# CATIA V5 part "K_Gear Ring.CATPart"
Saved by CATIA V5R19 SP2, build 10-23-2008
Part number: Gear Ring
Bounding box of the stored display mesh (mm): x -39.5 to 39.5, y -39.5 to 39.5, z -6 to 12
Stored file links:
  G:\Khaled_CFAO_2011\ST2M\ST2M_GR1\bgaltie\bgaltie\Khaled\CAD_thinkMOTION\K_Gear Ring.CATPart
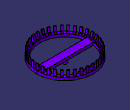
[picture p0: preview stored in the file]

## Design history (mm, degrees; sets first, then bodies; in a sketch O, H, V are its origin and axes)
AxisSystem1: origin (0, 0, 0), X (1, 0, 0), Y (0, 1, 0), Z (0, 0, 1)
Body1 (main body)
  Sketch1 on XY plane of AxisSystem1, origin (0, 0, 0), H (1, 0, 0), V (0, 1, 0)
    arc A1 centre (0, 0) radius 39.5 from (-39.5, 0) to (39.5, 0) ccw
    point P1 (0, 0)
    point P2 (39.5, 0)
    arc A2 centre (0, 0) radius 35 from (-34.641, -5) to (34.641, -5) ccw
    point P3 (0, 0)
    reference projected point E1 (0, 0) from vertex [YZ plane of AxisSystem1 | ZX plane of AxisSystem1 | XY plane of AxisSystem1]
    point P4 (34.641, -5)
    point P5 (-34.641, -5)
    line L1 (-34.641, -5) -> (34.641, -5)
    point P6 (-34.641, -5)
    point P7 (34.641, -5)
    reference projected point E2 (0, 0) from vertex [YZ plane of AxisSystem1 | ZX plane of AxisSystem1 | XY plane of AxisSystem1]
    line L2 (39.5, 0) -> (-39.5, 0)
    radius A1 = 39.5
    radius A2 = 35
    length L2 = 79
    distance L2 L1 = 5
    coincidence: P2 H, P3 E1, P4 P7, P6 P5, P1 E2
  Pad1: profile Sketch1, direction (0, 0, 1), length 4
  Mirror1: of Pad1, Sketch1, about ZX plane of AxisSystem1
  Sketch2 on face of Mirror1, origin (0, 0, 0), H (1, 0, 0), V (0, -1, 0)
    circle A1 centre (0, 0) radius 3
    point P1 (0, 0)
    radius A1 = 3
    coincidence: P1 O
  Pad2: profile Sketch2, direction (0, 0, -1), length 6
  Sketch3 on ZX plane of AxisSystem1, origin (0, 0, 0), H (0, 0, 1), V (1, 0, 0)
    line L1 (12, 39) -> (4, 39)
    line L2 (4, 39) -> (4, 35)
    line L3 (4, 35) -> (6.5, 35)
    line L4 (6.5, 35) -> (6.5, 36.5)
    line L5 (6.5, 36.5) -> (12, 38)
    line L6 (12, 38) -> (12, 39)
    reference projected line E1 (4, -39.5) -> (4, 39.5) from edge [face of Pad1 from Sketch1.A1 | face of Mirror1]
    reference projected line E2 (0, 39.5) -> (4, 39.5) from edge [face of Mirror1 | face of Pad1 from Sketch1.A1]
    length L2 = 4
    length L4 = 1.5
    length L3 = 2.5
    length L1 = 8
    distance L2 E1 = 0
    distance E2 L1 = 0.5
    length L6 = 1
    horizontal: L1 H, L3 H
    vertical: L2 V, L4 V, L6 V
  Pad3: profile Sketch3, direction (0, 1, 0), length 1.5, mirrored extent
  CircPattern1: of Pad3, instances 36, angular step 10, axis from edge [ZX plane of AxisSystem1 | YZ plane of AxisSystem1]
